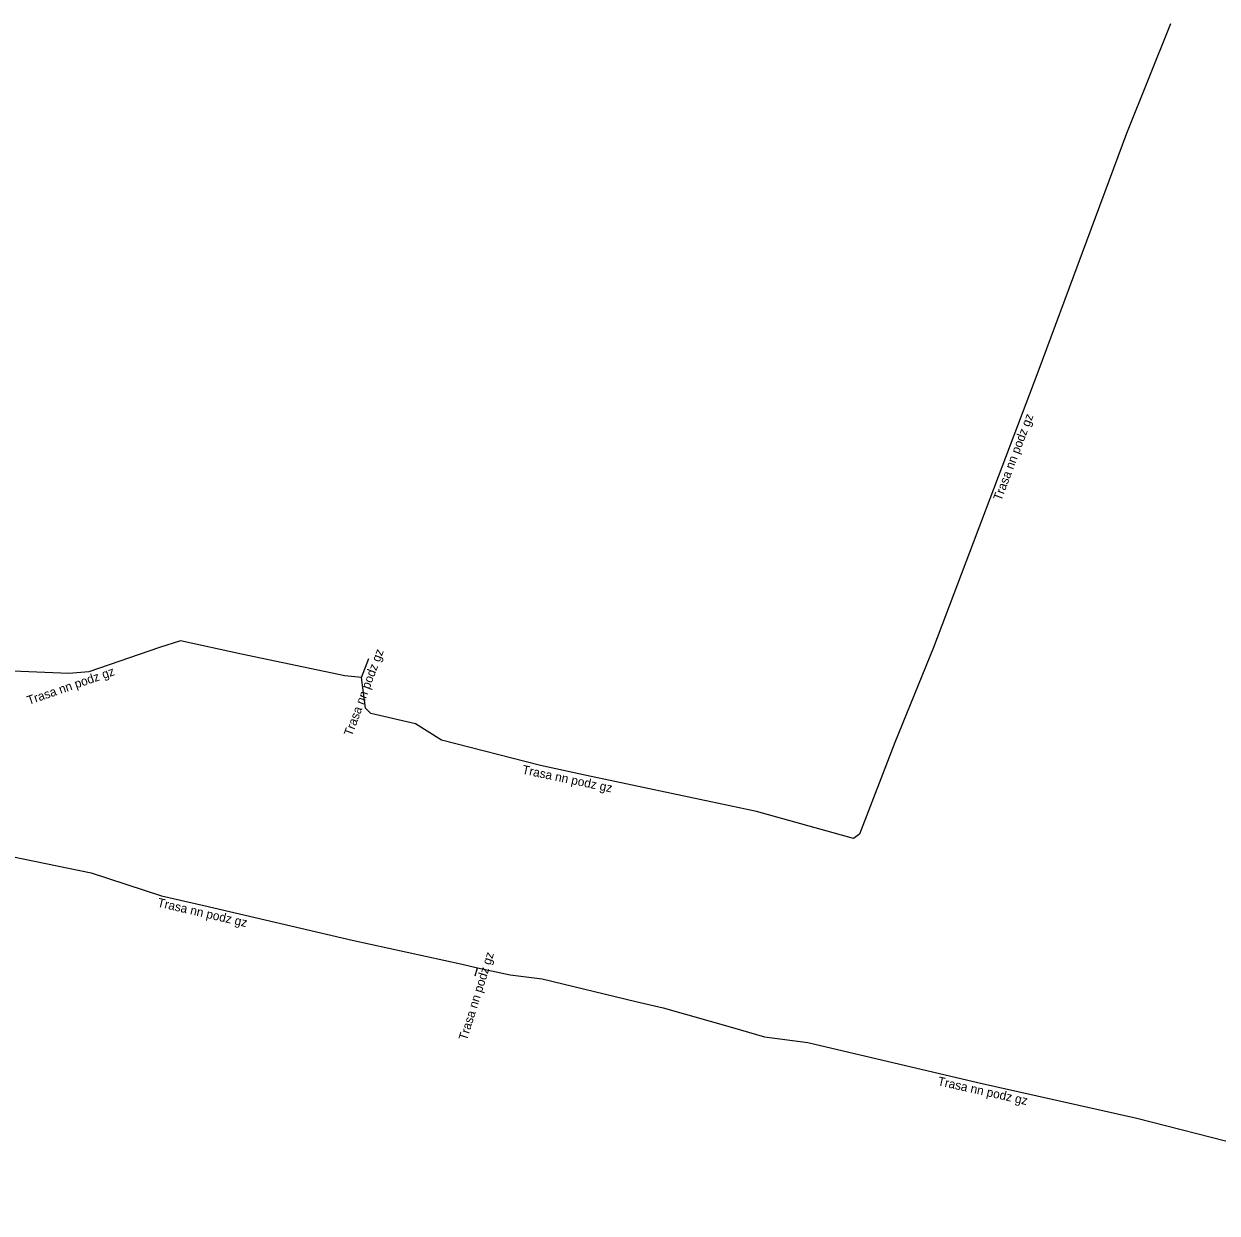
# Model space of a CAD drawing. Extents: x -771127 to -770600, y -1049993 to -1049871.
# Drawn here: x -770913.8 to -770846.6, y -1049938.6 to -1049871.6 of the extents above; entities that cross this region are included whole.
import ezdxf

# ---------------------------------------------------------------- set-up
doc = ezdxf.new("R2010")
doc.units = 0
doc.layers.add('Popiskový text - Ostatní atributy Trasy', color=7, linetype='Continuous')
doc.layers.add('Spojnice NN', color=7, linetype='Continuous')

msp = doc.modelspace()

# ---------------------------------------------------------------- linework, layer by layer
at = {"layer": 'Spojnice NN'}
for points in [[(-770849.208, -1049871.625), (-770851.69, -1049877.81), (-770856.69, -1049891.25), (-770862.56, -1049906.76), (-770864.74, -1049912.12), (-770866.74, -1049917.28), (-770867.06, -1049917.53)], [(-770894.77, -1049908.46), (-770895.72, -1049908.36), (-770901.53, -1049907.14), (-770904.97, -1049906.4), (-770906.15, -1049906.76), (-770910.13, -1049908.14), (-770911.26, -1049908.24), (-770915.34, -1049908.06), (-770916.73, -1049907.87), (-770917.24, -1049907.66), (-770921, -1049905.3), (-770923.68, -1049903.85), (-770924.27, -1049903.49), (-770924.086, -1049903.205)], [(-770894.77, -1049908.46), (-770894.371, -1049907.39)], [(-770867.06, -1049917.53), (-770872.54, -1049916), (-770882.11, -1049913.98), (-770884.7, -1049913.42), (-770890.27, -1049911.99), (-770891.74, -1049911.07), (-770894.26, -1049910.48), (-770894.55, -1049910.19), (-770894.77, -1049908.46)], [(-770916.146, -1049919.137), (-770916.149, -1049919.119), (-770915.71, -1049918.54), (-770914.47, -1049918.54), (-770910.01, -1049919.47), (-770906.04, -1049920.76), (-770903.65, -1049921.31), (-770895.3, -1049923.25), (-770889.11, -1049924.61), (-770888.24, -1049924.81)], [(-770888.38, -1049925.26), (-770888.24, -1049924.81)], [(-770888.24, -1049924.81), (-770886.4, -1049925.21), (-770884.61, -1049925.43), (-770879.32, -1049926.71), (-770877.79, -1049927.07), (-770873.89, -1049928.18), (-770872.08, -1049928.7), (-770869.65, -1049929.03), (-770859.99, -1049931.29), (-770851.12, -1049933.28), (-770845.23, -1049934.8), (-770840.82, -1049935.92), (-770837.26, -1049936.55), (-770829.89, -1049938.37), (-770828.62, -1049938.64)]]:
    msp.add_lwpolyline(points, dxfattribs=at)

# ---------------------------------------------------------------- texts
at = {"layer": 'Popiskový text - Ostatní atributy Trasy'}
for rotation, p in [(69.27007, (-770858.753, -1049898.538)), (69.54966, (-770895.322, -1049911.801)), (19.12315, (-770913.517, -1049910.003)), (348.08117, (-770885.763, -1049913.873)), (346.92022, (-770906.306, -1049921.36)), (72.7185, (-770888.846, -1049928.946)), (347.35497, (-770862.362, -1049931.424))]:
    msp.add_text('Trasa nn podz gz', height=0.5, rotation=rotation, dxfattribs=at).set_placement(p)

doc.saveas('drawing.dxf')
